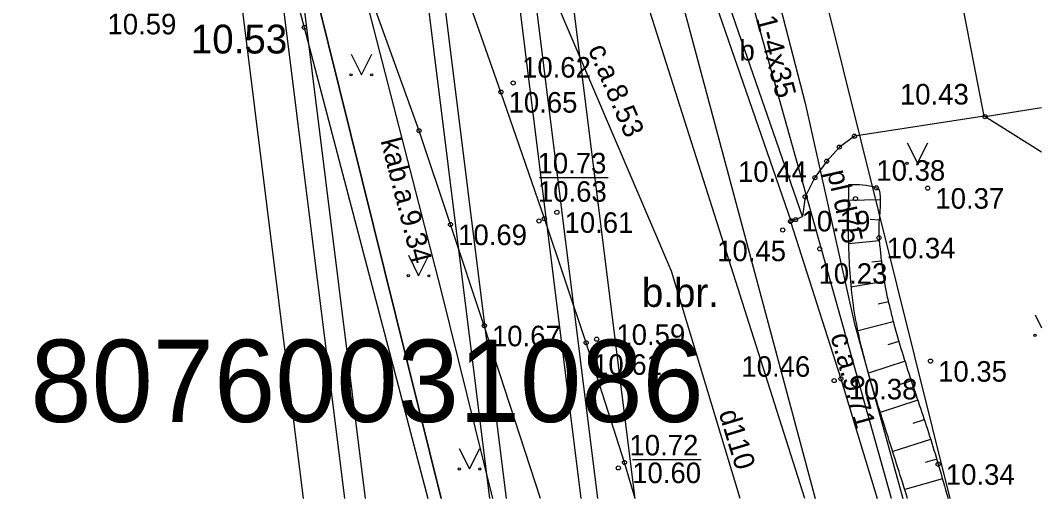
# Model space of a CAD drawing. Extents: x 502312.8 to 502402.4, y 308528.5 to 308602.
# Drawn here: x 502377.59 to 502402.41, y 308528.54 to 308540.16 of the extents above; entities that cross this region are included whole.
import ezdxf

# ---------------------------------------------------------------- set-up
doc = ezdxf.new("R2010")
doc.units = 0
for name, color, linetype in [('24', 7, 'Continuous'), ('59', 7, 'Continuous'), ('APGR_SARK_####_####_#', 7, 'Continuous'), ('APGS_ACRL_####_####_#', 7, 'Continuous'), ('APGS_ACRL_####_TKST_#', 7, 'Continuous'), ('APGS_VADP_ZSPR_####_I', 7, 'Continuous'), ('APGS_VADP_ZSPR_TKST_I', 7, 'Continuous'), ('BUVE_BDET_####_####_#', 7, 'Continuous'), ('BUVE_BDET_####_TKST_#', 7, 'Continuous'), ('CELI_CAPM_####_####_#', 7, 'Continuous'), ('CELI_CMAL_####_####_#', 7, 'Continuous'), ('CELI_CSEG_####_TKST_#', 7, 'Continuous'), ('CELI_SEGL_####_####_#', 7, 'Continuous'), ('ELEK_VADP_ZSPR_####_#', 7, 'Continuous'), ('ELEK_VADP_ZSPR_TKST_#', 7, 'Continuous'), ('ELEK_VADV_ASP1_####_#', 7, 'Continuous'), ('NORB_ZOGS_ZSTP_####_#', 7, 'Continuous'), ('RELJ_AATZ_####_TKST_#', 7, 'Continuous'), ('RELJ_ELEM_####_####_#', 7, 'Continuous'), ('RELJ_NOGA_####_####_#', 7, 'Continuous'), ('RELJ_NOGL_####_####_#', 7, 'Continuous'), ('SAKK_KKAN_####_####_#', 7, 'Continuous'), ('SKAN_ELEM_PAST_TKST_#', 7, 'Continuous'), ('SKAN_VADP_PAST_####_I', 7, 'Continuous'), ('TERT_ELEM_####_####_#', 7, 'Continuous'), ('UDTK_VADP_UDEN_####_#', 7, 'Continuous'), ('UDTK_VADP_UDEN_TKST_#', 7, 'Continuous')]:
    doc.layers.add(name, color=color, linetype=linetype)

msp = doc.modelspace()

# ---------------------------------------------------------------- linework, layer by layer
at = {"layer": '24'}
for p, q in [((502396.655, 308528.536), (502389.895, 308549.798)), ((502383.407, 308546.304), (502387.818, 308528.536))]:
    msp.add_line(p, q, dxfattribs=at)
at = {"layer": 'APGR_SARK_####_####_#'}
for p, q in [((502400.182, 308528.536), (502394.734, 308550.484)), ((502387.818, 308528.536), (502383.407, 308546.304))]:
    msp.add_line(p, q, dxfattribs=at)
at = {"layer": 'APGS_ACRL_####_####_#'}
msp.add_lwpolyline([(502392.92, 308547.155), (502393.176, 308547.21), (502393.742, 308547.379), (502394.027, 308547.306), (502394.296, 308546.179), (502395.166, 308543.945), (502396.665, 308538.15), (502397.857, 308532.815), (502399.035, 308528.536)], dxfattribs=at)
at = {"layer": 'APGS_VADP_ZSPR_####_I'}
msp.add_lwpolyline([(502392.92, 308547.155), (502393.176, 308547.21), (502393.742, 308547.379), (502394.027, 308547.306), (502394.296, 308546.179), (502395.166, 308543.945), (502396.665, 308538.15), (502397.857, 308532.815), (502399.035, 308528.536)], dxfattribs=at)
at = {"layer": 'BUVE_BDET_####_####_#'}
msp.add_lwpolyline([(502393.988, 308542.93), (502393.813, 308542.867), (502393.705, 308542.827), (502396.317, 308535.286), (502396.43, 308535.317), (502396.601, 308535.389), (502393.988, 308542.93)], dxfattribs=at)
at = {"layer": 'CELI_CAPM_####_####_#'}
for points in [[(502392.53, 308528.536), (502392.273, 308529.412), (502391.34, 308532.322), (502390.324, 308535.341), (502389.269, 308538.416), (502388.272, 308541.254), (502387.358, 308543.683), (502386.314, 308546.51), (502385.198, 308549.256), (502384.849, 308550.113), (502383.229, 308553.89), (502382.013, 308556.65), (502380.717, 308559.374), (502377.909, 308565.152), (502373.303, 308574.647)], [(502396.317, 308535.286), (502396.306, 308535.27), (502397.531, 308531.447), (502398.408, 308528.536)]]:
    msp.add_lwpolyline(points, dxfattribs=at)
at = {"layer": 'CELI_CMAL_####_####_#'}
for points in [[(502390.232, 308528.536), (502388.865, 308532.737), (502388.043, 308535.197), (502387.28, 308537.476), (502386.263, 308540.301), (502385.235, 308543.076), (502384.524, 308544.988), (502383.511, 308547.559), (502382.468, 308550.05), (502379.873, 308556.046), (502379.438, 308556.939), (502376.448, 308563.104), (502371.317, 308573.674)], [(502402.407, 308538.034), (502401.035, 308537.817)], [(502401.013, 308537.831), (502397.86, 308537.343), (502397.493, 308537.079), (502397.185, 308536.736), (502396.899, 308536.336), (502396.663, 308535.871), (502396.601, 308535.389)], [(502402.407, 308536.952), (502401.013, 308537.831)]]:
    msp.add_lwpolyline(points, dxfattribs=at)
at = {"layer": 'CELI_SEGL_####_####_#'}
msp.add_line((502401.013, 308537.831), (502400.224, 308541.903), dxfattribs=at)
at = {"layer": 'ELEK_VADP_ZSPR_####_#'}
for p, q in [((502383.39, 308550.751), (502387.809, 308533.607)), ((502387.809, 308533.607), (502389.068, 308528.536))]:
    msp.add_line(p, q, dxfattribs=at)
at = {"layer": 'ELEK_VADV_ASP1_####_#'}
msp.add_line((502392.53, 308528.536), (502385.08, 308588.302), dxfattribs=at)
for points in [[(502389.406, 308528.536), (502381.98, 308588.115)], [(502391.22, 308528.536), (502383.78, 308588.224)], [(502391.623, 308528.536), (502384.18, 308588.248)], [(502384.469, 308528.536), (502377.051, 308588.051)], [(502385.476, 308528.536), (502378.08, 308587.88)], [(502385.98, 308528.536), (502378.58, 308587.91)], [(502389.003, 308528.536), (502381.58, 308588.091)]]:
    msp.add_lwpolyline(points, dxfattribs=at)
at = {"layer": 'NORB_ZOGS_ZSTP_####_#'}
for p, q in [((502383.641, 308543.141), (502384.49, 308539.988)), ((502384.49, 308539.988), (502387.493, 308528.536))]:
    msp.add_line(p, q, dxfattribs=at)
at = {"layer": 'RELJ_AATZ_####_TKST_#'}
for p, q in [((502390.208, 308536.34), (502391.876, 308536.34)), ((502392.468, 308529.488), (502394.136, 308529.488))]:
    msp.add_line(p, q, dxfattribs=at)
at = {"layer": 'RELJ_ELEM_####_####_#'}
for centre in [(502384.49, 308539.988), (502389.567, 308538.637), (502389.269, 308538.416), (502401.035, 308537.817), (502387.28, 308537.476), (502397.86, 308537.343), (502397.493, 308537.079), (502397.185, 308536.736), (502396.899, 308536.336), (502398.394, 308536.089), (502399.641, 308536.081), (502396.663, 308535.871), (502397.885, 308535.827), (502390.629, 308535.494), (502390.195, 308535.283), (502390.324, 308535.341), (502396.306, 308535.27), (502396.317, 308535.286), (502396.43, 308535.317), (502388.043, 308535.197), (502396.118, 308535.065), (502398.457, 308534.874), (502397.017, 308534.606), (502388.865, 308532.737), (502391.34, 308532.322), (502391.595, 308532.409), (502399.707, 308531.877), (502397.368, 308531.404), (502397.531, 308531.447), (502392.121, 308529.281), (502392.273, 308529.412), (502399.895, 308529.371)]:
    msp.add_circle(centre, 0.05, dxfattribs=at)
at = {"layer": 'RELJ_NOGA_####_####_#'}
for p, q in [((502397.725, 308536.171), (502397.725, 308536.17)), ((502398.487, 308535.8), (502397.725, 308535.78)), ((502398.461, 308535.3), (502398.24, 308535.317)), ((502398.464, 308534.801), (502397.725, 308534.729)), ((502398.514, 308534.304), (502398.28, 308534.278)), ((502398.583, 308533.809), (502397.776, 308533.675)), ((502398.685, 308533.319), (502398.435, 308533.261)), ((502398.804, 308532.834), (502397.947, 308532.614)), ((502398.937, 308532.352), (502398.675, 308532.274)), ((502399.089, 308531.875), (502398.2, 308531.584)), ((502399.244, 308531.4), (502398.973, 308531.311)), ((502399.4, 308530.925), (502398.487, 308530.625)), ((502399.556, 308530.45), (502399.281, 308530.36)), ((502399.712, 308529.975), (502398.792, 308529.677)), ((502399.858, 308529.497), (502399.582, 308529.416)), ((502399.997, 308529.016), (502399.085, 308528.754)), ((502400.135, 308528.536), (502400.134, 308528.536))]:
    msp.add_line(p, q, dxfattribs=at)
msp.add_spline([(502397.725, 308536.171), (502398.394, 308536.089), (502398.443, 308536.06), (502398.469, 308535.998), (502398.485, 308535.852), (502398.483, 308535.607), (502398.465, 308535.362), (502398.45, 308535.118), (502398.457, 308534.874), (502398.491, 308534.522), (502398.53, 308534.171), (502398.649, 308533.472), (502398.732, 308533.123), (502398.818, 308532.778), (502399.016, 308532.096), (502399.463, 308530.733), (502399.687, 308530.053), (502399.895, 308529.371), (502400.135, 308528.536)], degree=3, dxfattribs=at)
at = {"layer": 'RELJ_NOGL_####_####_#'}
msp.add_spline([(502399.152, 308528.536), (502398.676, 308530.035), (502398.213, 308531.537), (502397.863, 308533.052), (502397.725, 308534.592), (502397.725, 308536.171)], degree=3, dxfattribs=at)
at = {"layer": 'SAKK_KKAN_####_####_#'}
msp.add_lwpolyline([(502398.757, 308528.536), (502394.797, 308542.663), (502393.046, 308548.902)], dxfattribs=at)
at = {"layer": 'SKAN_VADP_PAST_####_I'}
msp.add_lwpolyline([(502373.002, 308587.759), (502378.517, 308576.782), (502387.809, 308557.18), (502392.481, 308545.051), (502396.902, 308528.536)], dxfattribs=at)
at = {"layer": 'TERT_ELEM_####_####_#'}
for p, q in [((502385.629, 308539.335), (502385.879, 308538.835)), ((502385.879, 308538.835), (502386.129, 308539.335)), ((502399.14, 308537.185), (502399.39, 308536.685)), ((502399.39, 308536.685), (502399.64, 308537.185)), ((502387.019, 308534.451), (502387.269, 308533.951)), ((502387.269, 308533.951), (502387.519, 308534.451)), ((502402.25, 308533), (502402.407, 308532.685)), ((502388.258, 308529.755), (502388.508, 308529.255)), ((502388.508, 308529.255), (502388.758, 308529.755))]:
    msp.add_line(p, q, dxfattribs=at)
for centre, radius in [((502385.629, 308538.835), 0.028), ((502386.129, 308538.835), 0.0263), ((502399.139, 308536.684), 0.028), ((502399.639, 308536.684), 0.0263), ((502387.018, 308533.951), 0.028), ((502387.518, 308533.951), 0.0263), ((502402.25, 308532.5), 0.028), ((502388.258, 308529.255), 0.028), ((502388.758, 308529.255), 0.0263)]:
    msp.add_circle(centre, radius, dxfattribs=at)
at = {"layer": 'UDTK_VADP_UDEN_####_#'}
for p, q in [((502393.411, 308534.064), (502387.742, 308547.347)), ((502395.085, 308528.536), (502393.411, 308534.064))]:
    msp.add_line(p, q, dxfattribs=at)

# ---------------------------------------------------------------- texts
at = {"layer": '59'}
msp.add_text('80760031086', height=2, dxfattribs=at).set_placement((502377.835, 308530.397))
at = {"layer": 'APGS_ACRL_####_TKST_#'}
for s, rotation, p in [('pl d75', 282.5947, (502397.193, 308536.474)), ('c.a.9.71', 285.3876, (502397.271, 308532.494))]:
    msp.add_text(s, height=0.5, rotation=rotation, dxfattribs=at).set_placement(p)
at = {"layer": 'APGS_VADP_ZSPR_TKST_I'}
msp.add_text('AXPK 1-4x35', height=0.5, rotation=284.5029, dxfattribs=at).set_placement((502394.967, 308542.12))
at = {"layer": 'BUVE_BDET_####_TKST_#'}
msp.add_text('b', height=0.5, dxfattribs=at).set_placement((502395.067, 308539.181))
at = {"layer": 'CELI_CSEG_####_TKST_#'}
msp.add_text('b.br.', height=0.7, dxfattribs=at).set_placement((502392.694, 308533.195))
at = {"layer": 'ELEK_VADP_ZSPR_TKST_#'}
msp.add_text('kab.a.9.34', height=0.5, rotation=284.4151, dxfattribs=at).set_placement((502386.341, 308537.235))
at = {"layer": 'RELJ_AATZ_####_TKST_#'}
for s, height, p in [('10.53', 0.7, (502381.733, 308539.354)), (' 10.62', 0.5, (502389.597, 308538.767)), (' 10.43', 0.5, (502398.779, 308538.114)), (' 10.65', 0.5, (502389.269, 308537.916)), (' 10.73', 0.5, (502389.973, 308536.439)), (' 10.38', 0.5, (502398.207, 308536.261)), (' 10.44', 0.5, (502394.844, 308536.231)), (' 10.63', 0.5, (502389.982, 308535.749)), (' 10.37', 0.5, (502399.641, 308535.581)), (' 10.19', 0.5, (502396.388, 308535.029)), (' 10.61', 0.5, (502390.629, 308534.994)), (' 10.69', 0.5, (502388.043, 308534.697)), (' 10.45', 0.5, (502394.338, 308534.306)), (' 10.34', 0.5, (502398.457, 308534.374)), (' 10.23', 0.5, (502396.801, 308533.756)), (' 10.59', 0.5, (502391.889, 308532.271)), (' 10.67', 0.5, (502388.865, 308532.237)), (' 10.61', 0.5, (502391.323, 308531.543)), (' 10.46', 0.5, (502394.927, 308531.496)), (' 10.35', 0.5, (502399.707, 308531.377)), (' 10.38', 0.5, (502397.531, 308530.947)), (' 10.72', 0.5, (502392.207, 308529.584)), (' 10.60', 0.5, (502392.273, 308528.912)), (' 10.34', 0.5, (502399.895, 308528.871))]:
    msp.add_text(s, height=height, dxfattribs=at).set_placement(p)
at = {"layer": 'SKAN_ELEM_PAST_TKST_#'}
msp.add_text('10.59', height=0.5, dxfattribs=at).set_placement((502379.708, 308539.818))
at = {"layer": 'UDTK_VADP_UDEN_TKST_#'}
for s, rotation, p in [('c.a.8.53', 293.1113, (502391.376, 308539.459)), ('d110', 286.8492, (502394.558, 308530.621))]:
    msp.add_text(s, height=0.5, rotation=rotation, dxfattribs=at).set_placement(p)

doc.saveas('drawing.dxf')
